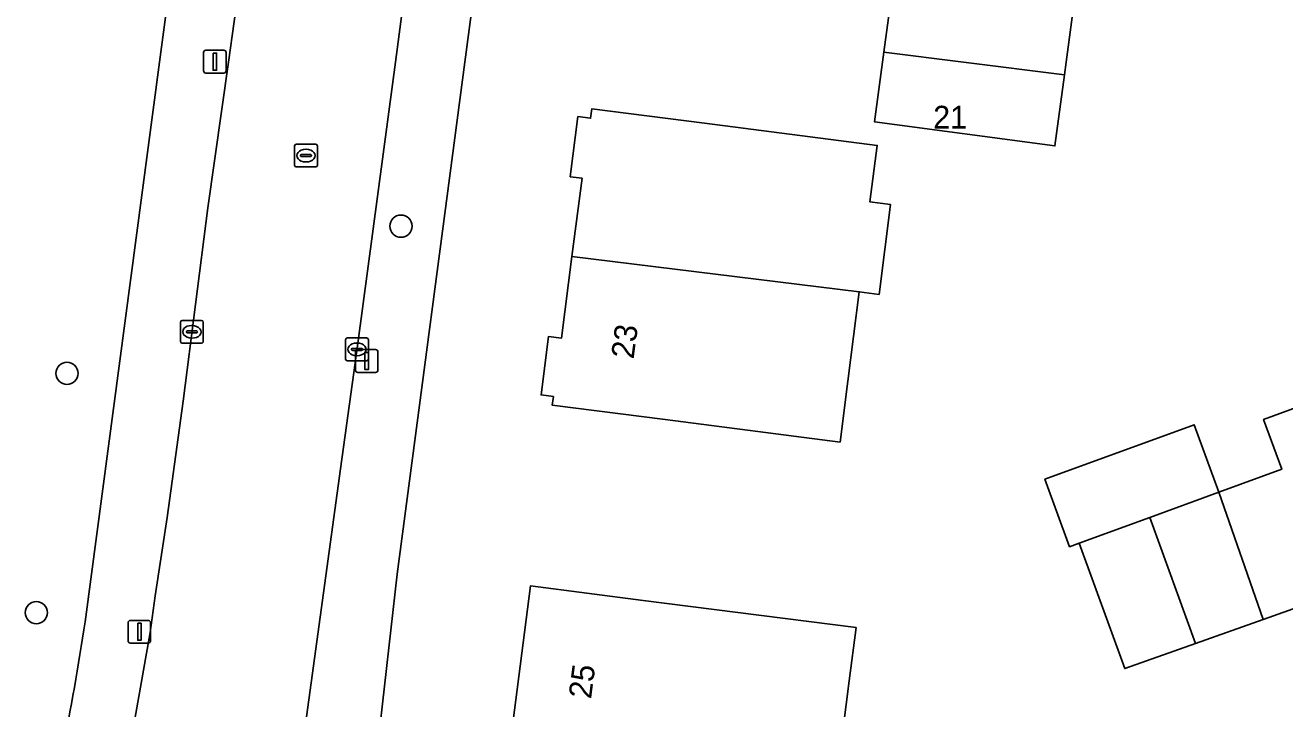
# Model space of a CAD drawing. Extents: x 161258 to 161838, y 380833 to 381727.
# Drawn here: x 161555.5 to 161610.9, y 381471.6 to 381501.6 of the extents above; entities that cross this region are included whole.
import ezdxf

# ---------------------------------------------------------------- set-up
doc = ezdxf.new("R2010")
doc.units = 0
for name, color, linetype in [('IMGEO_Boom', 7, 'Continuous'), ('IMGEO_Erf', 7, 'Continuous'), ('IMGEO_Groenvoorziening', 7, 'Continuous'), ('IMGEO_Kolk', 7, 'Continuous'), ('IMGEO_Lichtmast', 7, 'Continuous'), ('IMGEO_Pand', 7, 'Continuous'), ('IMGEO_Pand_nummerreeks', 7, 'Continuous'), ('IMGEO_Rijbaan_lokaal_open', 7, 'Continuous'), ('IMGEO_Rioolput', 7, 'Continuous'), ('IMGEO_Voetpad_open', 7, 'Continuous')]:
    doc.layers.add(name, color=color, linetype=linetype)

msp = doc.modelspace()

# ---------------------------------------------------------------- linework, layer by layer
at = {"layer": 'IMGEO_Boom'}
for centre in [(161572.049, 381492.782), (161557.365, 381486.31), (161556.016, 381475.788)]:
    msp.add_circle(centre, 0.489, dxfattribs=at)
at = {"layer": 'IMGEO_Erf'}
for points in [[(161586.507, 381587.885), (161574.866, 381500), (161571.884, 381477.487), (161571.043, 381470.087), (161570.912, 381467.059)], [(161601.617, 381502.414), (161601.298, 381500), (161601.224, 381499.44), (161600.809, 381496.313), (161592.879, 381497.364), (161593.286, 381500.441), (161593.659, 381503.252)], [(161582.08, 381458.989), (161605.707, 381467.743), (161606.375, 381467.99), (161614.726, 381471.084), (161615.03, 381471.197), (161639.66, 381480.333), (161637.901, 381485.076), (161631.731, 381482.822), (161625.653, 381480.602), (161619.737, 381478.442), (161619.615, 381478.397), (161619.445, 381478.863), (161609.959, 381475.49), (161606.995, 381474.436), (161603.876, 381473.327), (161601.876, 381478.837), (161601.451, 381478.682), (161600.366, 381481.654), (161606.926, 381484.051), (161608.011, 381481.079), (161610.784, 381482.092), (161609.984, 381484.283), (161613.737, 381485.653), (161613.409, 381486.551)]]:
    msp.add_lwpolyline(points, dxfattribs=at)
for points in [[(161591.358, 381483.289), (161583.662, 381484.275), (161578.702, 381484.91), (161578.751, 381485.291), (161578.214, 381485.36), (161578.544, 381487.933), (161579.112, 381487.86), (161579.571, 381491.443), (161580.012, 381494.889), (161579.493, 381494.955), (161579.832, 381497.6), (161580.385, 381497.529), (161580.437, 381497.94), (161585.397, 381497.305), (161592.991, 381496.332), (161592.673, 381493.846), (161593.58, 381493.73), (161593.075, 381489.784), (161592.204, 381489.895), (161591.7, 381485.963)], [(161591.763, 381472.786), (161591.128, 381467.826), (161583.526, 381468.799), (161583.499, 381468.587), (161576.779, 381469.447), (161577.742, 381476.962), (161582.702, 381476.327), (161592.063, 381475.128)]]:
    msp.add_lwpolyline(points, close=True, dxfattribs=at)
at = {"layer": 'IMGEO_Groenvoorziening'}
msp.add_lwpolyline([(161558.161, 381475.388), (161561.438, 381500), (161572.354, 381581.996)], dxfattribs=at)
msp.add_arc((161436.621, 381493.719), 122.914, 345.96834, 351.42332, dxfattribs=at)
at = {"layer": 'IMGEO_Kolk'}
for p, q in [((161562.357, 381487.71), (161562.357, 381488.562)), ((161562.432, 381488.636), (161563.284, 381488.636)), ((161562.616, 381488.13), (161562.616, 381488.142)), ((161562.659, 381488.179), (161563.057, 381488.179)), ((161562.845, 381488.416), (161562.87, 381488.416)), ((161563.1, 381488.142), (161563.1, 381488.13)), ((161563.358, 381488.562), (161563.358, 381487.71)), ((161563.284, 381487.636), (161562.432, 381487.636)), ((161563.054, 381488.093), (161562.656, 381488.093)), ((161562.868, 381487.856), (161562.843, 381487.856)), ((161569.615, 381486.939), (161569.615, 381487.791)), ((161569.69, 381487.865), (161570.542, 381487.865)), ((161570.103, 381487.645), (161570.128, 381487.645)), ((161570.616, 381487.791), (161570.616, 381486.939)), ((161569.874, 381487.359), (161569.874, 381487.371)), ((161570.312, 381487.322), (161569.914, 381487.322)), ((161569.917, 381487.408), (161570.315, 381487.408)), ((161570.126, 381487.085), (161570.101, 381487.085)), ((161570.358, 381487.371), (161570.358, 381487.359)), ((161570.542, 381486.865), (161569.69, 381486.865))]:
    msp.add_line(p, q, dxfattribs=at)
for points in [[(161562.357, 381487.71), (161562.357, 381488.562)], [(161562.432, 381488.636), (161563.284, 381488.636)], [(161563.358, 381488.562), (161563.358, 381487.71)], [(161563.284, 381487.636), (161562.432, 381487.636)], [(161569.615, 381486.939), (161569.615, 381487.791)], [(161569.69, 381487.865), (161570.542, 381487.865)], [(161570.616, 381487.791), (161570.616, 381486.939)], [(161570.542, 381486.865), (161569.69, 381486.865)]]:
    msp.add_lwpolyline(points, dxfattribs=at)
for centre, radius, start, end in [((161562.434, 381488.56), 0.0765, 91.552, 178.448), ((161562.434, 381488.56), 0.0765, 91.552, 178.448), ((161562.656, 381488.139), 0.0403, 85.8775, 175.7526), ((161562.653, 381488.129), 0.0366, 178.938, 274.7102), ((161563.057, 381488.136), 0.043, 264.8664, 352.4533), ((161563.061, 381488.141), 0.0386, 1.7309, 96.639), ((161563.282, 381488.56), 0.0765, 1.552, 88.448), ((161563.282, 381488.56), 0.0765, 1.552, 88.448), ((161562.434, 381487.712), 0.0765, 181.552, 268.448), ((161562.434, 381487.712), 0.0765, 181.552, 268.448), ((161563.282, 381487.712), 0.0765, 271.552, 358.448), ((161563.282, 381487.712), 0.0765, 271.552, 358.448), ((161569.692, 381487.789), 0.0765, 91.552, 178.448), ((161569.692, 381487.789), 0.0765, 91.552, 178.448), ((161570.54, 381487.789), 0.0765, 1.552, 88.448), ((161570.54, 381487.789), 0.0765, 1.552, 88.448), ((161569.914, 381487.368), 0.0403, 85.8775, 175.7526), ((161569.911, 381487.358), 0.0366, 178.938, 274.7102), ((161570.315, 381487.365), 0.043, 264.8664, 352.4533), ((161570.319, 381487.37), 0.0386, 1.7309, 96.639), ((161569.692, 381486.941), 0.0765, 181.552, 268.448), ((161569.692, 381486.941), 0.0765, 181.552, 268.448), ((161570.54, 381486.941), 0.0765, 271.552, 358.448), ((161570.54, 381486.941), 0.0765, 271.552, 358.448)]:
    msp.add_arc(centre, radius, start, end, dxfattribs=at)
for centre, major_axis, ratio, start_param, end_param in [((161562.844, 381488.136), (-0.387, 0.002), 0.722429, 4.712389, 7.853982), ((161562.869, 381488.136), (-0.39, 0.002), 0.717154, 1.570796, 4.712389), ((161570.102, 381487.365), (-0.387, 0.002), 0.722429, 4.712389, 7.853982), ((161570.127, 381487.365), (-0.39, 0.002), 0.717154, 1.570796, 4.712389)]:
    msp.add_ellipse(centre, major_axis=major_axis, ratio=ratio, start_param=start_param, end_param=end_param, dxfattribs=at)
at = {"layer": 'IMGEO_Lichtmast'}
for p, q in [((161563.371, 381499.617), (161563.371, 381500.417)), ((161563.371, 381500.417), (161563.371, 381499.617)), ((161563.471, 381500.517), (161564.261, 381500.517)), ((161564.261, 381500.517), (161563.471, 381500.517)), ((161564.361, 381500.417), (161564.361, 381499.617)), ((161564.361, 381499.617), (161564.361, 381500.417)), ((161564.261, 381499.517), (161563.471, 381499.517)), ((161563.471, 381499.517), (161564.261, 381499.517)), ((161570.047, 381486.453), (161570.047, 381487.253)), ((161570.047, 381487.253), (161570.047, 381486.453)), ((161570.147, 381487.353), (161570.937, 381487.353)), ((161570.937, 381487.353), (161570.147, 381487.353)), ((161571.037, 381487.253), (161571.037, 381486.453)), ((161571.037, 381486.453), (161571.037, 381487.253)), ((161570.937, 381486.353), (161570.147, 381486.353)), ((161570.147, 381486.353), (161570.937, 381486.353)), ((161560.154, 381475.447), (161560.944, 381475.447)), ((161560.944, 381475.447), (161560.154, 381475.447)), ((161560.054, 381474.547), (161560.054, 381475.347)), ((161560.054, 381475.347), (161560.054, 381474.547)), ((161561.044, 381475.347), (161561.044, 381474.547)), ((161561.044, 381474.547), (161561.044, 381475.347)), ((161560.944, 381474.447), (161560.154, 381474.447)), ((161560.154, 381474.447), (161560.944, 381474.447))]:
    msp.add_line(p, q, dxfattribs=at)
for points in [[(161563.791, 381500.392), (161563.941, 381500.392), (161563.941, 381499.642), (161563.791, 381499.642), (161563.791, 381500.392)], [(161570.467, 381487.228), (161570.617, 381487.228), (161570.617, 381486.478), (161570.467, 381486.478), (161570.467, 381487.228)], [(161560.474, 381475.322), (161560.624, 381475.322), (161560.624, 381474.572), (161560.474, 381474.572), (161560.474, 381475.322)]]:
    msp.add_lwpolyline(points, dxfattribs=at)
for centre, start, end in [((161563.471, 381500.417), 90, 180), ((161563.471, 381500.417), 90, 180), ((161564.261, 381500.417), 0, 90), ((161564.261, 381500.417), 360, 90), ((161563.471, 381499.617), 180, 270), ((161563.471, 381499.617), 180, 270), ((161564.261, 381499.617), 270, 0), ((161564.261, 381499.617), 270, 0), ((161570.147, 381487.253), 90, 180), ((161570.147, 381487.253), 90, 180), ((161570.937, 381487.253), 0, 90), ((161570.937, 381487.253), 360, 90), ((161570.147, 381486.453), 180, 270), ((161570.147, 381486.453), 180, 270), ((161570.937, 381486.453), 270, 0), ((161570.937, 381486.453), 270, 0), ((161560.154, 381475.347), 90, 180), ((161560.154, 381475.347), 90, 180), ((161560.944, 381475.347), 0, 90), ((161560.944, 381475.347), 360, 90), ((161560.154, 381474.547), 180, 270), ((161560.154, 381474.547), 180, 270), ((161560.944, 381474.547), 270, 0), ((161560.944, 381474.547), 270, 0)]:
    msp.add_arc(centre, 0.1, start, end, dxfattribs=at)
at = {"layer": 'IMGEO_Pand'}
for points in [[(161594.883, 381510.908), (161582.39, 381512.492), (161581.905, 381508.833), (161581.371, 381508.903), (161581.037, 381506.376), (161581.545, 381506.309), (161581.494, 381505.923), (161586.451, 381505.266), (161588.731, 381504.964), (161588.593, 381503.923), (161593.659, 381503.252), (161593.286, 381500.441), (161596.785, 381500), (161601.224, 381499.44), (161601.298, 381500), (161601.617, 381502.414), (161593.885, 381503.39), (161594.001, 381504.266), (161594.374, 381507.076)], [(161601.224, 381499.44), (161596.785, 381500), (161593.286, 381500.441), (161592.879, 381497.364), (161600.809, 381496.313)], [(161592.204, 381489.895), (161593.075, 381489.784), (161593.58, 381493.73), (161592.673, 381493.846), (161592.991, 381496.332), (161585.397, 381497.305), (161580.437, 381497.94), (161580.385, 381497.529), (161579.832, 381497.6), (161579.493, 381494.955), (161580.012, 381494.889), (161579.571, 381491.443)], [(161591.7, 381485.963), (161592.204, 381489.895), (161579.571, 381491.443), (161579.112, 381487.86), (161578.544, 381487.933), (161578.214, 381485.36), (161578.751, 381485.291), (161578.702, 381484.91), (161583.662, 381484.275), (161591.358, 381483.289)], [(161615.228, 381490.728), (161614.359, 381490.41), (161613.908, 381490.245), (161611.962, 381489.535), (161613.099, 381486.438), (161613.409, 381486.551), (161613.737, 381485.653), (161609.984, 381484.283), (161610.784, 381482.092), (161608.011, 381481.079), (161609.959, 381475.49), (161619.445, 381478.863), (161619.615, 381478.397), (161619.737, 381478.442)], [(161601.876, 381478.837), (161604.973, 381479.969), (161608.011, 381481.079), (161606.926, 381484.051), (161600.366, 381481.654), (161601.451, 381478.682)], [(161609.959, 381475.49), (161608.011, 381481.079), (161604.973, 381479.969), (161606.995, 381474.436)], [(161606.995, 381474.436), (161604.973, 381479.969), (161601.876, 381478.837), (161603.876, 381473.327)], [(161582.702, 381476.327), (161577.742, 381476.962), (161576.779, 381469.447), (161583.499, 381468.587), (161583.526, 381468.799), (161591.128, 381467.826), (161591.763, 381472.786), (161592.063, 381475.128)]]:
    msp.add_lwpolyline(points, close=True, dxfattribs=at)
at = {"layer": 'IMGEO_Rijbaan_lokaal_open'}
msp.add_lwpolyline([(161564.97, 381503.589), (161564.461, 381500), (161563.551, 381493.584), (161562.472, 381485.086), (161561.767, 381479.974), (161561.243, 381476.529), (161561.022, 381474.922), (161560.397, 381471.348), (161559.659, 381466.987), (161558.66, 381462.845), (161566.653, 381461.801), (161566.898, 381463.819), (161567.603, 381469.069), (161569.393, 381482.117), (161569.975, 381486.348), (161570.167, 381487.742), (161571.673, 381499.011), (161571.805, 381500), (161572.723, 381506.947)], dxfattribs=at)
at = {"layer": 'IMGEO_Rioolput'}
for p, q in [((161567.373, 381495.461), (161567.373, 381496.313)), ((161567.448, 381496.387), (161568.3, 381496.387)), ((161567.632, 381495.881), (161567.632, 381495.893)), ((161567.675, 381495.93), (161568.073, 381495.93)), ((161567.861, 381496.167), (161567.886, 381496.167)), ((161568.116, 381495.893), (161568.116, 381495.881)), ((161568.374, 381496.313), (161568.374, 381495.461)), ((161568.3, 381495.387), (161567.448, 381495.387)), ((161568.07, 381495.844), (161567.672, 381495.844)), ((161567.884, 381495.607), (161567.859, 381495.607))]:
    msp.add_line(p, q, dxfattribs=at)
for points in [[(161567.373, 381495.461), (161567.373, 381496.313)], [(161567.448, 381496.387), (161568.3, 381496.387)], [(161568.374, 381496.313), (161568.374, 381495.461)], [(161568.3, 381495.387), (161567.448, 381495.387)]]:
    msp.add_lwpolyline(points, dxfattribs=at)
for centre, radius, start, end in [((161567.45, 381496.311), 0.0765, 91.552, 178.448), ((161567.45, 381496.311), 0.0765, 91.552, 178.448), ((161567.672, 381495.89), 0.0403, 85.8775, 175.7526), ((161567.669, 381495.88), 0.0366, 178.938, 274.7102), ((161568.073, 381495.887), 0.043, 264.8664, 352.4533), ((161568.077, 381495.892), 0.0386, 1.7309, 96.639), ((161568.298, 381496.311), 0.0765, 1.552, 88.448), ((161568.298, 381496.311), 0.0765, 1.552, 88.448), ((161567.45, 381495.463), 0.0765, 181.552, 268.448), ((161567.45, 381495.463), 0.0765, 181.552, 268.448), ((161568.298, 381495.463), 0.0765, 271.552, 358.448), ((161568.298, 381495.463), 0.0765, 271.552, 358.448)]:
    msp.add_arc(centre, radius, start, end, dxfattribs=at)
for centre, major_axis, ratio, start_param, end_param in [((161567.86, 381495.887), (-0.387, 0.002), 0.722429, 4.712389, 7.853982), ((161567.885, 381495.887), (-0.39, 0.002), 0.717154, 1.570796, 4.712389)]:
    msp.add_ellipse(centre, major_axis=major_axis, ratio=ratio, start_param=start_param, end_param=end_param, dxfattribs=at)
at = {"layer": 'IMGEO_Voetpad_open'}
for points in [[(161569.179, 381453.691), (161571.043, 381470.087), (161571.884, 381477.487), (161574.866, 381500), (161586.507, 381587.885)], [(161561.767, 381479.974), (161562.472, 381485.086), (161563.551, 381493.584), (161564.461, 381500), (161564.97, 381503.589), (161566.277, 381513.264), (161567.769, 381525.137), (161569.138, 381534.992), (161570.675, 381546.225), (161571.88, 381555.532), (161572.882, 381563.041), (161574.137, 381572.407), (161575.172, 381580.435), (161575.751, 381584.539), (161576.004, 381586.446), (161576.131, 381587.471)], [(161572.877, 381585.329), (161572.824, 381584.999), (161572.395, 381582.307), (161572.354, 381581.996), (161561.438, 381500), (161558.161, 381475.388)], [(161572.723, 381506.947), (161571.805, 381500), (161571.673, 381499.011), (161570.167, 381487.742), (161569.975, 381486.348), (161569.393, 381482.117), (161567.603, 381469.069), (161566.898, 381463.819), (161566.653, 381461.801), (161566.646, 381461.74), (161566.395, 381459.656)], [(161558.66, 381462.845), (161559.659, 381466.987), (161560.397, 381471.348), (161561.022, 381474.922), (161561.243, 381476.529), (161561.767, 381479.974)]]:
    msp.add_lwpolyline(points, dxfattribs=at)
msp.add_arc((161436.621, 381493.719), 122.914, 345.96834, 351.42332, dxfattribs=at)

# ---------------------------------------------------------------- texts
at = {"layer": 'IMGEO_Pand_nummerreeks'}
msp.add_text('21', height=1, dxfattribs=at).set_placement((161595.454, 381497.076))
for s, rotation, p in [('23', 82.4142, (161582.278, 381486.916)), ('25', 82.6977, (161580.409, 381471.968))]:
    msp.add_text(s, height=1, rotation=rotation, dxfattribs=at).set_placement(p)

doc.saveas('drawing.dxf')
